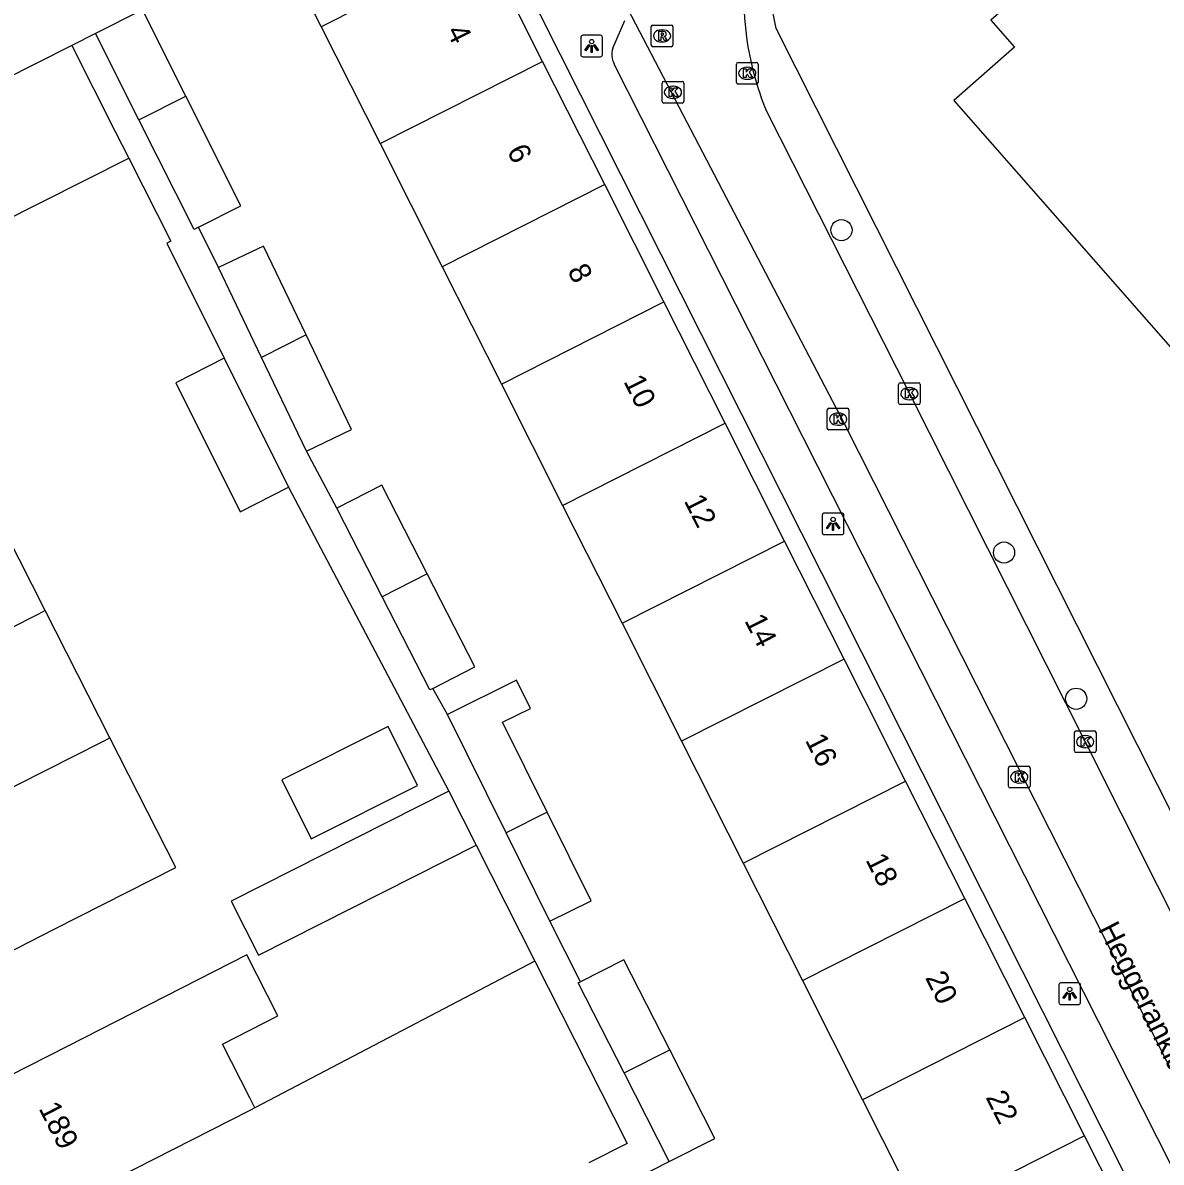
# Model space of a CAD drawing. Extents: x 162347 to 162868, y 381221 to 381813.
# Drawn here: x 162397.4 to 162450, y 381601.3 to 381653.9 of the extents above; entities that cross this region are included whole.
import ezdxf

# ---------------------------------------------------------------- set-up
doc = ezdxf.new("R2010")
doc.units = 0
for name, color, linetype in [('IMGEO_Boom', 7, 'Continuous'), ('IMGEO_Kolk', 7, 'Continuous'), ('IMGEO_Lichtpunt', 7, 'Continuous'), ('IMGEO_Openbare_ruimte_label', 7, 'Continuous'), ('IMGEO_Pand', 7, 'Continuous'), ('IMGEO_Pand_nummerreeks', 7, 'Continuous'), ('IMGEO_Rijbaan_lokaal_open', 7, 'Continuous'), ('IMGEO_Rioolput', 7, 'Continuous'), ('IMGEO_Voetpad_open', 7, 'Continuous')]:
    doc.layers.add(name, color=color, linetype=linetype)

msp = doc.modelspace()

# ---------------------------------------------------------------- linework, layer by layer
at = {"layer": 'IMGEO_Boom'}
for centre in [(162435.249, 381644.33), (162442.757, 381629.448), (162446.087, 381622.699)]:
    msp.add_circle(centre, 0.489, dxfattribs=at)
at = {"layer": 'IMGEO_Kolk'}
for p, q in [((162430.399, 381651.144), (162430.399, 381651.996)), ((162430.474, 381652.07), (162431.326, 381652.07)), ((162430.887, 381651.85), (162430.912, 381651.85)), ((162431.4, 381651.996), (162431.4, 381651.144)), ((162430.91, 381651.29), (162430.885, 381651.29)), ((162426.969, 381650.266), (162426.969, 381651.118)), ((162427.044, 381651.192), (162427.896, 381651.192)), ((162427.457, 381650.972), (162427.482, 381650.972)), ((162427.97, 381651.118), (162427.97, 381650.266)), ((162431.326, 381651.07), (162430.474, 381651.07)), ((162427.48, 381650.412), (162427.455, 381650.412)), ((162427.896, 381650.192), (162427.044, 381650.192)), ((162437.885, 381636.356), (162437.885, 381637.208)), ((162437.96, 381637.282), (162438.812, 381637.282)), ((162438.886, 381637.208), (162438.886, 381636.356)), ((162438.373, 381637.062), (162438.398, 381637.062)), ((162434.595, 381635.179), (162434.595, 381636.031)), ((162434.67, 381636.105), (162435.522, 381636.105)), ((162435.596, 381636.031), (162435.596, 381635.179)), ((162438.812, 381636.282), (162437.96, 381636.282)), ((162438.396, 381636.502), (162438.371, 381636.502)), ((162435.083, 381635.885), (162435.108, 381635.885)), ((162435.522, 381635.105), (162434.67, 381635.105)), ((162435.106, 381635.325), (162435.081, 381635.325)), ((162446.003, 381620.291), (162446.003, 381621.143)), ((162446.078, 381621.217), (162446.93, 381621.217)), ((162446.491, 381620.997), (162446.516, 381620.997)), ((162447.004, 381621.143), (162447.004, 381620.291)), ((162446.514, 381620.437), (162446.489, 381620.437)), ((162446.93, 381620.217), (162446.078, 381620.217)), ((162442.957, 381618.657), (162442.957, 381619.509)), ((162443.032, 381619.583), (162443.884, 381619.583)), ((162443.445, 381619.363), (162443.47, 381619.363)), ((162443.958, 381619.509), (162443.958, 381618.657)), ((162443.468, 381618.803), (162443.443, 381618.803)), ((162443.884, 381618.583), (162443.032, 381618.583))]:
    msp.add_line(p, q, dxfattribs=at)
for points in [[(162430.399, 381651.144), (162430.399, 381651.996)], [(162430.474, 381652.07), (162431.326, 381652.07)], [(162431.4, 381651.996), (162431.4, 381651.144)], [(162430.72, 381651.77), (162430.843, 381651.77), (162430.843, 381651.619), (162430.973, 381651.77), (162431.137, 381651.77), (162430.991, 381651.619), (162431.144, 381651.37), (162430.992, 381651.37), (162430.907, 381651.534), (162430.843, 381651.467), (162430.843, 381651.37), (162430.72, 381651.37), (162430.72, 381651.77)], [(162426.969, 381650.266), (162426.969, 381651.118)], [(162427.044, 381651.192), (162427.896, 381651.192)], [(162427.29, 381650.892), (162427.413, 381650.892), (162427.413, 381650.741), (162427.543, 381650.892), (162427.707, 381650.892), (162427.561, 381650.741), (162427.714, 381650.492), (162427.562, 381650.492), (162427.477, 381650.656), (162427.413, 381650.589), (162427.413, 381650.492), (162427.29, 381650.492), (162427.29, 381650.892)], [(162427.97, 381651.118), (162427.97, 381650.266)], [(162431.326, 381651.07), (162430.474, 381651.07)], [(162427.896, 381650.192), (162427.044, 381650.192)], [(162437.885, 381636.356), (162437.885, 381637.208)], [(162437.96, 381637.282), (162438.812, 381637.282)], [(162438.886, 381637.208), (162438.886, 381636.356)], [(162438.206, 381636.982), (162438.329, 381636.982), (162438.329, 381636.831), (162438.459, 381636.982), (162438.623, 381636.982), (162438.477, 381636.831), (162438.63, 381636.582), (162438.478, 381636.582), (162438.393, 381636.746), (162438.329, 381636.679), (162438.329, 381636.582), (162438.206, 381636.582), (162438.206, 381636.982)], [(162434.595, 381635.179), (162434.595, 381636.031)], [(162434.67, 381636.105), (162435.522, 381636.105)], [(162435.596, 381636.031), (162435.596, 381635.179)], [(162438.812, 381636.282), (162437.96, 381636.282)], [(162434.916, 381635.805), (162435.039, 381635.805), (162435.039, 381635.654), (162435.169, 381635.805), (162435.333, 381635.805), (162435.187, 381635.654), (162435.34, 381635.405), (162435.188, 381635.405), (162435.103, 381635.569), (162435.039, 381635.502), (162435.039, 381635.405), (162434.916, 381635.405), (162434.916, 381635.805)], [(162435.522, 381635.105), (162434.67, 381635.105)], [(162446.003, 381620.291), (162446.003, 381621.143)], [(162446.078, 381621.217), (162446.93, 381621.217)], [(162446.324, 381620.917), (162446.447, 381620.917), (162446.447, 381620.766), (162446.577, 381620.917), (162446.741, 381620.917), (162446.595, 381620.766), (162446.748, 381620.517), (162446.596, 381620.517), (162446.511, 381620.681), (162446.447, 381620.614), (162446.447, 381620.517), (162446.324, 381620.517), (162446.324, 381620.917)], [(162447.004, 381621.143), (162447.004, 381620.291)], [(162446.93, 381620.217), (162446.078, 381620.217)], [(162442.957, 381618.657), (162442.957, 381619.509)], [(162443.032, 381619.583), (162443.884, 381619.583)], [(162443.278, 381619.283), (162443.401, 381619.283), (162443.401, 381619.132), (162443.531, 381619.283), (162443.695, 381619.283), (162443.549, 381619.132), (162443.702, 381618.883), (162443.55, 381618.883), (162443.465, 381619.047), (162443.401, 381618.98), (162443.401, 381618.883), (162443.278, 381618.883), (162443.278, 381619.283)], [(162443.958, 381619.509), (162443.958, 381618.657)], [(162443.884, 381618.583), (162443.032, 381618.583)]]:
    msp.add_lwpolyline(points, dxfattribs=at)
for centre, start, end in [((162430.476, 381651.994), 91.552, 178.448), ((162430.476, 381651.994), 91.552, 178.448), ((162431.324, 381651.994), 1.552, 88.448), ((162431.324, 381651.994), 1.552, 88.448), ((162427.046, 381651.116), 91.552, 178.448), ((162427.046, 381651.116), 91.552, 178.448), ((162427.894, 381651.116), 1.552, 88.448), ((162427.894, 381651.116), 1.552, 88.448), ((162430.476, 381651.146), 181.552, 268.448), ((162430.476, 381651.146), 181.552, 268.448), ((162431.324, 381651.146), 271.552, 358.448), ((162431.324, 381651.146), 271.552, 358.448), ((162427.046, 381650.268), 181.552, 268.448), ((162427.046, 381650.268), 181.552, 268.448), ((162427.894, 381650.268), 271.552, 358.448), ((162427.894, 381650.268), 271.552, 358.448), ((162437.962, 381637.206), 91.552, 178.448), ((162437.962, 381637.206), 91.552, 178.448), ((162438.81, 381637.206), 1.552, 88.448), ((162438.81, 381637.206), 1.552, 88.448), ((162434.672, 381636.029), 91.552, 178.448), ((162434.672, 381636.029), 91.552, 178.448), ((162435.52, 381636.029), 1.552, 88.448), ((162435.52, 381636.029), 1.552, 88.448), ((162437.962, 381636.358), 181.552, 268.448), ((162437.962, 381636.358), 181.552, 268.448), ((162438.81, 381636.358), 271.552, 358.448), ((162438.81, 381636.358), 271.552, 358.448), ((162434.672, 381635.181), 181.552, 268.448), ((162434.672, 381635.181), 181.552, 268.448), ((162435.52, 381635.181), 271.552, 358.448), ((162435.52, 381635.181), 271.552, 358.448), ((162446.08, 381621.141), 91.552, 178.448), ((162446.08, 381621.141), 91.552, 178.448), ((162446.928, 381621.141), 1.552, 88.448), ((162446.928, 381621.141), 1.552, 88.448), ((162446.08, 381620.293), 181.552, 268.448), ((162446.08, 381620.293), 181.552, 268.448), ((162446.928, 381620.293), 271.552, 358.448), ((162446.928, 381620.293), 271.552, 358.448), ((162443.034, 381619.507), 91.552, 178.448), ((162443.034, 381619.507), 91.552, 178.448), ((162443.882, 381619.507), 1.552, 88.448), ((162443.882, 381619.507), 1.552, 88.448), ((162443.034, 381618.659), 181.552, 268.448), ((162443.034, 381618.659), 181.552, 268.448), ((162443.882, 381618.659), 271.552, 358.448), ((162443.882, 381618.659), 271.552, 358.448)]:
    msp.add_arc(centre, 0.0765, start, end, dxfattribs=at)
for centre, major_axis, ratio, start_param, end_param in [((162430.886, 381651.57), (-0.387, 0.002), 0.722429, 4.712389, 7.853982), ((162430.911, 381651.57), (-0.39, 0.002), 0.717154, 1.570796, 4.712389), ((162427.456, 381650.692), (-0.387, 0.002), 0.722429, 4.712389, 7.853982), ((162427.481, 381650.692), (-0.39, 0.002), 0.717154, 1.570796, 4.712389), ((162438.372, 381636.782), (-0.387, 0.002), 0.722429, 4.712389, 7.853982), ((162438.397, 381636.782), (-0.39, 0.002), 0.717154, 1.570796, 4.712389), ((162435.082, 381635.605), (-0.387, 0.002), 0.722429, 4.712389, 7.853982), ((162435.107, 381635.605), (-0.39, 0.002), 0.717154, 1.570796, 4.712389), ((162446.49, 381620.717), (-0.387, 0.002), 0.722429, 4.712389, 7.853982), ((162446.515, 381620.717), (-0.39, 0.002), 0.717154, 1.570796, 4.712389), ((162443.444, 381619.083), (-0.387, 0.002), 0.722429, 4.712389, 7.853982), ((162443.469, 381619.083), (-0.39, 0.002), 0.717154, 1.570796, 4.712389)]:
    msp.add_ellipse(centre, major_axis=major_axis, ratio=ratio, start_param=start_param, end_param=end_param, dxfattribs=at)
at = {"layer": 'IMGEO_Lichtpunt'}
for p, q in [((162423.216, 381653.232), (162423.216, 381652.425)), ((162423.216, 381653.232), (162423.216, 381652.425)), ((162424.118, 381653.327), (162423.31, 381653.327)), ((162424.118, 381653.327), (162423.31, 381653.327)), ((162424.212, 381652.425), (162424.212, 381653.232)), ((162424.212, 381652.425), (162424.212, 381653.232)), ((162423.31, 381652.331), (162424.118, 381652.331)), ((162423.31, 381652.331), (162424.118, 381652.331)), ((162434.364, 381631.176), (162434.364, 381630.369)), ((162434.364, 381631.176), (162434.364, 381630.369)), ((162435.266, 381631.271), (162434.458, 381631.271)), ((162435.266, 381631.271), (162434.458, 381631.271)), ((162435.36, 381630.369), (162435.36, 381631.176)), ((162435.36, 381630.369), (162435.36, 381631.176)), ((162434.458, 381630.275), (162435.266, 381630.275)), ((162434.458, 381630.275), (162435.266, 381630.275)), ((162445.29, 381609.487), (162445.29, 381608.68)), ((162445.29, 381609.487), (162445.29, 381608.68)), ((162446.192, 381609.582), (162445.384, 381609.582)), ((162446.192, 381609.582), (162445.384, 381609.582)), ((162446.286, 381608.68), (162446.286, 381609.487)), ((162446.286, 381608.68), (162446.286, 381609.487)), ((162445.384, 381608.586), (162446.192, 381608.586)), ((162445.384, 381608.586), (162446.192, 381608.586))]:
    msp.add_line(p, q, dxfattribs=at)
for points in [[(162423.59, 381652.896), (162423.629, 381652.868), (162423.441, 381652.606), (162423.403, 381652.633), (162423.59, 381652.896)], [(162423.802, 381652.868), (162423.84, 381652.895), (162424.027, 381652.633), (162423.988, 381652.605), (162423.802, 381652.868)], [(162423.692, 381652.848), (162423.739, 381652.848), (162423.739, 381652.526), (162423.692, 381652.526), (162423.692, 381652.848)], [(162434.738, 381630.84), (162434.777, 381630.812), (162434.589, 381630.55), (162434.551, 381630.577), (162434.738, 381630.84)], [(162434.84, 381630.792), (162434.887, 381630.792), (162434.887, 381630.47), (162434.84, 381630.47), (162434.84, 381630.792)], [(162434.95, 381630.812), (162434.988, 381630.839), (162435.175, 381630.577), (162435.136, 381630.549), (162434.95, 381630.812)], [(162445.664, 381609.151), (162445.703, 381609.123), (162445.515, 381608.861), (162445.477, 381608.888), (162445.664, 381609.151)], [(162445.766, 381609.103), (162445.813, 381609.103), (162445.813, 381608.781), (162445.766, 381608.781), (162445.766, 381609.103)], [(162445.876, 381609.123), (162445.914, 381609.15), (162446.101, 381608.888), (162446.062, 381608.86), (162445.876, 381609.123)]]:
    msp.add_lwpolyline(points, dxfattribs=at)
for centre in [(162423.715, 381653.03), (162434.863, 381630.974), (162445.789, 381609.285)]:
    msp.add_circle(centre, 0.0994, dxfattribs=at)
for centre, start, end in [((162423.31, 381653.232), 90, 180), ((162423.31, 381653.232), 90, 180), ((162424.118, 381653.232), 0, 90), ((162424.118, 381653.232), 0, 90), ((162423.31, 381652.425), 180, 270), ((162423.31, 381652.425), 180, 270), ((162424.118, 381652.425), 270, 0), ((162424.118, 381652.425), 270, 360), ((162434.458, 381631.176), 90, 180), ((162434.458, 381631.176), 90, 180), ((162435.266, 381631.176), 0, 90), ((162435.266, 381631.176), 0, 90), ((162434.458, 381630.369), 180, 270), ((162434.458, 381630.369), 180, 270), ((162435.266, 381630.369), 270, 0), ((162435.266, 381630.369), 270, 360), ((162445.384, 381609.487), 90, 180), ((162445.384, 381609.487), 90, 180), ((162446.192, 381609.487), 0, 90), ((162446.192, 381609.487), 0, 90), ((162445.384, 381608.68), 180, 270), ((162445.384, 381608.68), 180, 270), ((162446.192, 381608.68), 270, 0), ((162446.192, 381608.68), 270, 360)]:
    msp.add_arc(centre, 0.0946, start, end, dxfattribs=at)
at = {"layer": 'IMGEO_Pand'}
for points in [[(162461.097, 381635.067), (162463.598, 381632.222), (162472.178, 381639.917), (162469.109, 381643.41), (162467.852, 381642.305), (162466.539, 381643.799), (162467.795, 381644.904), (162457.226, 381656.932), (162459.336, 381658.786), (162457.216, 381661.198), (162455.031, 381659.277), (162453.049, 381661.533), (162450.273, 381659.093), (162449.248, 381660.259), (162442.142, 381654.015), (162443.233, 381652.774), (162440.439, 381650.319), (162457.002, 381631.47), (162461.097, 381635.067)], [(162408.443, 381659.219), (162411.223, 381653.711)], [(162418.73, 381657.511), (162411.223, 381653.711)], [(162421.45, 381652.12), (162418.73, 381657.511)], [(162404.977, 381650.514), (162402.978, 381654.492), (162400.813, 381653.404)], [(162402.812, 381649.427), (162400.813, 381653.404)], [(162411.223, 381653.711), (162413.943, 381648.322)], [(162399.713, 381652.851), (162391.711, 381648.827), (162394.326, 381643.627), (162402.34, 381647.657)], [(162399.713, 381652.851), (162401.722, 381648.879), (162402.34, 381647.657)], [(162413.943, 381648.322), (162421.45, 381652.12)], [(162424.321, 381646.43), (162421.45, 381652.12)], [(162402.812, 381649.427), (162404.977, 381650.514)], [(162405.563, 381644.464), (162407.524, 381645.45), (162404.977, 381650.514)], [(162405.563, 381644.464), (162405.359, 381644.361), (162402.812, 381649.427)], [(162413.943, 381648.322), (162416.815, 381642.631)], [(162424.321, 381646.43), (162416.815, 381642.631)], [(162427.054, 381641.014), (162424.321, 381646.43)], [(162410.531, 381639.492), (162408.559, 381643.596), (162406.484, 381642.6)], [(162408.473, 381638.458), (162406.484, 381642.6)], [(162416.815, 381642.631), (162419.549, 381637.215)], [(162419.549, 381637.215), (162427.054, 381641.014)], [(162429.874, 381635.425), (162427.054, 381641.014)], [(162410.531, 381639.492), (162408.473, 381638.458)], [(162410.555, 381634.126), (162412.63, 381635.122), (162410.531, 381639.492)], [(162406.749, 381638.413), (162404.519, 381637.283), (162407.493, 381631.334), (162409.724, 381632.464)], [(162406.749, 381638.413), (162409.724, 381632.464)], [(162410.555, 381634.126), (162408.473, 381638.458)], [(162419.549, 381637.215), (162422.369, 381631.627)], [(162422.369, 381631.627), (162429.874, 381635.425)], [(162432.623, 381629.979), (162429.874, 381635.425)], [(162398.481, 381626.77), (162395.465, 381632.697)], [(162416.12, 381628.465), (162414.024, 381632.562), (162411.946, 381631.498)], [(162414.037, 381627.411), (162411.946, 381631.498)], [(162422.369, 381631.627), (162425.117, 381626.182)], [(162425.117, 381626.182), (162432.623, 381629.979)], [(162435.371, 381624.533), (162432.623, 381629.979)], [(162416.12, 381628.465), (162414.037, 381627.411)], [(162416.38, 381623.18), (162418.317, 381624.171), (162416.12, 381628.465)], [(162416.38, 381623.18), (162416.239, 381623.108), (162414.037, 381627.411)], [(162398.481, 381626.77), (162398.14, 381626.591), (162389.157, 381622.048)], [(162401.468, 381620.899), (162398.481, 381626.77)], [(162425.117, 381626.182), (162427.866, 381620.735)], [(162435.371, 381624.533), (162427.866, 381620.735)], [(162438.213, 381618.9), (162436.297, 381622.697), (162435.371, 381624.533)], [(162421.661, 381617.459), (162419.6, 381621.619), (162420.889, 381622.257), (162420.243, 381623.56), (162417.052, 381621.979)], [(162419.764, 381616.506), (162417.052, 381621.979)], [(162409.403, 381618.959), (162410.76, 381616.241), (162415.676, 381618.696), (162414.319, 381621.414), (162409.403, 381618.959)], [(162392.072, 381616.147), (162391.431, 381615.821), (162392.214, 381614.28), (162391.947, 381614.144), (162393.333, 381611.419), (162393.56, 381611.534), (162394.445, 381609.794), (162398.902, 381612.062), (162404.512, 381614.916), (162401.468, 381620.899)], [(162392.072, 381616.147), (162401.111, 381620.715), (162401.468, 381620.899)], [(162427.866, 381620.735), (162430.709, 381615.103)], [(162430.709, 381615.103), (162438.213, 381618.9)], [(162440.946, 381613.483), (162438.213, 381618.9)], [(162417.121, 381618.435), (162407.074, 381613.357), (162408.339, 381610.859), (162418.383, 381615.941)], [(162417.121, 381618.435), (162418.383, 381615.941)], [(162421.661, 381617.459), (162419.764, 381616.506)], [(162421.786, 381612.426), (162423.689, 381613.368), (162421.661, 381617.459)], [(162421.786, 381612.426), (162419.764, 381616.506)], [(162430.709, 381615.103), (162433.443, 381609.687)], [(162433.443, 381609.687), (162440.946, 381613.483)], [(162443.722, 381607.981), (162440.946, 381613.483)], [(162408.169, 381603.815), (162408.091, 381603.968), (162407.93, 381604.285), (162406.673, 381606.755), (162409.231, 381608.056), (162407.798, 381610.873), (162399.497, 381606.65), (162395.04, 381604.382), (162395.432, 381603.613), (162395.031, 381603.409), (162397.484, 381598.588), (162397.885, 381598.792), (162397.971, 381598.622), (162398.225, 381598.75)], [(162421.093, 381610.584), (162408.169, 381603.815)], [(162421.093, 381610.584), (162425.348, 381602.17), (162423.591, 381601.277)], [(162427.318, 381606.489), (162425.198, 381610.652), (162423.205, 381609.637)], [(162425.21, 381605.43), (162423.095, 381609.581), (162423.205, 381609.637)], [(162433.443, 381609.687), (162436.22, 381604.184)], [(162443.722, 381607.981), (162436.22, 381604.184)], [(162446.477, 381602.521), (162443.722, 381607.981)], [(162425.21, 381605.43), (162427.318, 381606.489)], [(162427.294, 381601.337), (162429.396, 381602.408), (162427.318, 381606.489)], [(162427.294, 381601.337), (162425.21, 381605.43)], [(162436.22, 381604.184), (162438.975, 381598.725)], [(162408.169, 381603.815), (162407.903, 381603.676), (162398.225, 381598.75)], [(162446.477, 381602.521), (162438.975, 381598.725)], [(162449.333, 381596.861), (162446.477, 381602.521)]]:
    msp.add_lwpolyline(points, dxfattribs=at)
at = {"layer": 'IMGEO_Rijbaan_lokaal_open'}
for points in [[(162425.373, 381654.562), (162435.395, 381635.369), (162459.045, 381588.618), (162459.315, 381588.084)], [(162431.784, 381649.823), (162438.386, 381636.782), (162446.504, 381620.717), (162454.794, 381604.194), (162462.238, 381589.534)]]:
    msp.add_lwpolyline(points, dxfattribs=at)
for centre, radius, start, end in [((162458.629, 381656.353), 27.94, 176.7455, 186.4172), ((162444.727, 381655.146), 13.995, 187.8682, 202.3544)]:
    msp.add_arc(centre, radius, start, end, dxfattribs=at)
at = {"layer": 'IMGEO_Rioolput'}
for p, q in [((162426.466, 381652.87), (162426.466, 381653.722)), ((162426.541, 381653.796), (162427.393, 381653.796)), ((162426.954, 381653.576), (162426.979, 381653.576)), ((162427.467, 381653.722), (162427.467, 381652.87)), ((162426.977, 381653.016), (162426.952, 381653.016)), ((162427.393, 381652.796), (162426.541, 381652.796))]:
    msp.add_line(p, q, dxfattribs=at)
for points in [[(162426.466, 381652.87), (162426.466, 381653.722)], [(162426.541, 381653.796), (162427.393, 381653.796)], [(162427.055, 381653.494), (162426.803, 381653.496), (162426.803, 381653.096)], [(162426.981, 381653.415), (162426.927, 381653.415), (162426.927, 381653.334)], [(162427.467, 381653.722), (162427.467, 381652.87)], [(162426.803, 381653.096), (162426.927, 381653.096), (162426.927, 381653.258), (162426.938, 381653.258)], [(162426.927, 381653.334), (162426.979, 381653.334)], [(162426.985, 381653.229), (162427.056, 381653.096), (162427.196, 381653.096), (162427.131, 381653.222)], [(162427.393, 381652.796), (162426.541, 381652.796)]]:
    msp.add_lwpolyline(points, dxfattribs=at)
for centre, radius, start, end in [((162426.543, 381653.72), 0.0765, 91.552, 178.448), ((162426.543, 381653.72), 0.0765, 91.552, 178.448), ((162426.987, 381653.319), 0.0964, 77.0061, 93.1865), ((162427.001, 381653.376), 0.0378, 276.6634, 79.6772), ((162427.054, 381653.384), 0.109, 350.3612, 89.416), ((162427.391, 381653.72), 0.0765, 1.552, 88.448), ((162427.391, 381653.72), 0.0765, 1.552, 88.448), ((162426.543, 381652.872), 0.0765, 181.552, 268.448), ((162426.543, 381652.872), 0.0765, 181.552, 268.448), ((162426.937, 381653.205), 0.0533, 26.0293, 88.6989), ((162426.963, 381653.523), 0.19, 274.7715, 282.9687), ((162427.052, 381653.384), 0.112, 277.5842, 350.9817), ((162427.036, 381653.169), 0.108, 29.5134, 73.7905), ((162427.391, 381652.872), 0.0765, 271.552, 358.448), ((162427.391, 381652.872), 0.0765, 271.552, 358.448)]:
    msp.add_arc(centre, radius, start, end, dxfattribs=at)
for centre, major_axis, ratio, start_param, end_param in [((162426.953, 381653.296), (-0.387, 0.002), 0.722429, 4.712389, 7.853982), ((162426.978, 381653.296), (-0.39, 0.002), 0.717154, 1.570796, 4.712389)]:
    msp.add_ellipse(centre, major_axis=major_axis, ratio=ratio, start_param=start_param, end_param=end_param, dxfattribs=at)
at = {"layer": 'IMGEO_Voetpad_open'}
for points in [[(162481.795, 381631.988), (162465.1, 381621.456), (162465.658, 381620.415), (162459.405, 381616.959), (162453.909, 381613.922), (162453.166, 381613.535), (162453.177, 381613.49), (162452.631, 381613.197), (162432.233, 381653.635), (162431.972, 381654.923), (162436.115, 381656.689), (162435.222, 381659.331), (162439.544, 381661.021), (162442.545, 381663.577), (162445.27, 381668.731), (162448.302, 381667.139), (162451.197, 381672.343), (162452.016, 381672.565)], [(162415.849, 381663.025), (162416.703, 381663.475), (162450.084, 381597.259), (162455.733, 381586.132)], [(162424.695, 381652.736), (162425.245, 381654.004)], [(162400.813, 381653.404), (162399.713, 381652.851)], [(162488.481, 381525.898), (162484.409, 381533.947), (162458.021, 381586.227), (162433.476, 381634.757), (162424.757, 381651.992)], [(162402.34, 381647.657), (162404.281, 381643.819), (162404.093, 381643.724), (162406.749, 381638.413)], [(162406.484, 381642.6), (162405.563, 381644.464)], [(162411.946, 381631.498), (162410.555, 381634.126)], [(162409.724, 381632.464), (162417.121, 381618.435)], [(162417.052, 381621.979), (162416.38, 381623.18)], [(162418.383, 381615.941), (162421.093, 381610.584)], [(162423.205, 381609.637), (162421.786, 381612.426)], [(162427.136, 381597.807), (162425.761, 381600.556), (162427.294, 381601.337)]]:
    msp.add_lwpolyline(points, dxfattribs=at)
msp.add_arc((162425.604, 381652.437), 0.957, 161.7938, 207.7334, dxfattribs=at)

# ---------------------------------------------------------------- texts
at = {"layer": 'IMGEO_Openbare_ruimte_label'}
msp.add_text('Heggeranklaan', height=1, rotation=296.8725, dxfattribs=at).set_placement((162447.083, 381612.081))
at = {"layer": 'IMGEO_Pand_nummerreeks'}
for s, rotation, p in [('4', 296.8429, (162416.989, 381653.508)), ('6', 296.8429, (162419.783, 381647.987)), ('8', 296.8429, (162422.579, 381642.461)), ('10', 296.8429, (162425.167, 381637.351)), ('12', 296.8429, (162427.958, 381631.835)), ('14', 296.8429, (162430.754, 381626.311)), ('16', 296.8429, (162433.549, 381620.789)), ('18', 296.8429, (162436.344, 381615.265)), ('20', 296.8429, (162439.097, 381609.824)), ('22', 296.8429, (162441.888, 381604.309)), ('189', 296.9689, (162398.168, 381603.793))]:
    msp.add_text(s, height=1, rotation=rotation, dxfattribs=at).set_placement(p)

doc.saveas('drawing.dxf')
